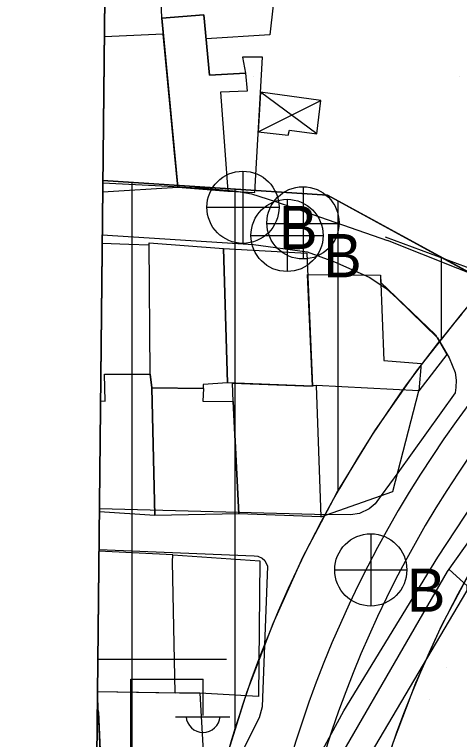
# Model space of a CAD drawing. Extents: x 417997 to 421451, y 4451742 to 4455216.
# Drawn here: x 419108.7 to 419151.9, y 4452992.2 to 4453062.5 of the extents above; entities that cross this region are included whole.
import ezdxf

# ---------------------------------------------------------------- set-up
doc = ezdxf.new("R2010")
doc.units = 0
for name, color, linetype in [('ADA', 7, 'Continuous'), ('ADAKENARI', 7, 'Continuous'), ('B_Mesken', 7, 'Continuous'), ('B_Sundurma', 7, 'Continuous'), ('B_Teras', 7, 'Continuous'), ('Default', 7, 'Continuous'), ('KALDIRIM', 7, 'Continuous'), ('O_Park_Bahce', 7, 'Continuous'), ('P_Grid', 7, 'Continuous'), ('PAFTALAMA', 7, 'Continuous'), ('PL_AYA_PARK_DINLENME', 7, 'Continuous'), ('PL_KON_MEV_350', 7, 'Continuous'), ('PL_SAY_ORTAOGRETIM', 7, 'Continuous'), ('S_Elektrik_Diregi', 7, 'Continuous'), ('S_Rogar_Kapagi', 7, 'Continuous'), ('S_Rogar_Kapagi_Buski', 7, 'Continuous'), ('Sinir_Duvar_tek_tarafa_ait', 7, 'Continuous'), ('Sinir_Tel_bir_taraf', 7, 'Continuous'), ('SN_3_DERECE_KAYNAK_KORUMA', 7, 'Continuous'), ('TR_ORTAEGITIM', 7, 'Continuous'), ('TR_ORTAYOGUNKONUT', 7, 'Continuous'), ('TR_PARKALANI', 7, 'Continuous'), ('Y_Lejant', 7, 'Continuous'), ('Yol_Sose', 7, 'Continuous')]:
    doc.layers.add(name, color=color, linetype=linetype)

# ---------------------------------------------------------------- blocks, each defined once
blk = doc.blocks.new('POINT_DISPLAY')
at = {"layer": 'Default'}
blk.add_line((0, 0), (0, 0), dxfattribs=at)

msp = doc.modelspace()

# ---------------------------------------------------------------- linework, layer by layer
at = {"layer": 'ADA'}
for p, q in [((419139.075, 4453044.969), (419117.291, 4453046.386)), ((419139.075, 4453044.969), (419117.291, 4453046.386)), ((419154.645, 4453036.476), (419139.075, 4453044.969)), ((419154.645, 4453036.476), (419139.075, 4453044.969))]:
    msp.add_line(p, q, dxfattribs=at)
at = {"layer": 'ADAKENARI'}
for centre, radius in [((419239.972, 4452959.278), 114.998), ((419239.972, 4452959.278), 114.998), ((419239.974, 4452959.277), 100), ((419239.974, 4452959.277), 100)]:
    msp.add_arc(centre, radius, 139.84982, 178.48545, dxfattribs=at)
at = {"layer": 'B_Mesken'}
for points in [[(419122.886, 4453065.646), (419131.262, 4453065.954), (419131.282, 4453066.278), (419134.125, 4453066.305), (419133.472, 4453060.53), (419127.307, 4453060.119), (419127.085, 4453062.473), (419123.008, 4453062.14)], [(419129.418, 4453045.377), (419132.029, 4453045.248), (419132.781, 4453058.357), (419130.841, 4453058.355), (419131.132, 4453056.792), (419127.637, 4453056.615), (419127.085, 4453062.473), (419123.008, 4453062.14), (419124.561, 4453045.747)], [(419121.893, 4453027.607), (419121.769, 4453040.345), (419129.002, 4453039.813), (419129.368, 4453026.782), (419127.03, 4453026.634), (419127.024, 4453026.219), (419122.051, 4453026.291)], [(419129.002, 4453039.813), (419137.064, 4453039.365), (419137.614, 4453026.472), (419129.368, 4453026.782)], [(419144.231, 4453036.536), (419149.567, 4453031.444), (419150.642, 4453029.514), (419147.947, 4453026.007), (419137.98, 4453026.513), (419137.614, 4453026.472), (419137.153, 4453037.272), (419144.204, 4453037.222)], [(419122.331, 4453013.908), (419122.051, 4453026.291), (419127.038, 4453026.218), (419126.999, 4453025), (419129.942, 4453024.987), (419130.484, 4453014.067)], [(419138.424, 4453013.795), (419130.484, 4453014.067), (419129.942, 4453024.987), (419129.88, 4453026.763), (419137.614, 4453026.472), (419137.611, 4453026.542), (419137.98, 4453026.513)], [(419137.98, 4453026.513), (419138.424, 4453013.795), (419145.417, 4453016.242), (419147.947, 4453026.007)], [(419124.313, 4452996.731), (419124.043, 4453009.437), (419124.066, 4453010.118), (419132.519, 4453009.525), (419132.388, 4452996.369), (419126.705, 4452996.688)], [(419117.349, 4452983.794), (419116.768, 4452996.867), (419126.705, 4452996.688), (419127.432, 4452983.718)]]:
    msp.add_lwpolyline(points, close=True, dxfattribs=at)
for points in [[(419117.281, 4453045.294), (419124.561, 4453045.747), (419123.156, 4453060.578), (419117.442, 4453060.325)], [(419117.064, 4453025.025), (419117.502, 4453025.008), (419117.443, 4453027.628), (419121.893, 4453027.607), (419122.051, 4453026.291), (419122.331, 4453013.908), (419116.949, 4453014.282)], [(419116.763, 4452996.869), (419116.768, 4452996.867), (419124.313, 4452996.731), (419124.043, 4453009.437), (419124.066, 4453010.118), (419116.909, 4453010.475)], [(419116.742, 4452994.893), (419116.856, 4452994.893), (419117.349, 4452983.794), (419116.623, 4452983.796)]]:
    msp.add_lwpolyline(points, dxfattribs=at)
at = {"layer": 'B_Sundurma'}
for p, q in [((419138.044, 4453050.922), (419132.586, 4453054.959)), ((419132.366, 4453051.124), (419138.444, 4453054.168))]:
    msp.add_line(p, q, dxfattribs=at)
msp.add_lwpolyline([(419132.366, 4453051.124), (419135.276, 4453050.79), (419135.39, 4453051.275), (419138.044, 4453050.922), (419138.444, 4453054.168), (419132.586, 4453054.959)], close=True, dxfattribs=at)
at = {"layer": 'B_Teras'}
for points in [[(419124.219, 4453049.361), (419123.008, 4453062.14), (419127.085, 4453062.473), (419127.637, 4453056.615), (419131.132, 4453056.792), (419131.282, 4453055.053), (419128.715, 4453054.966), (419129.13, 4453049.309), (419129.418, 4453045.377), (419124.561, 4453045.747)], [(419137.153, 4453037.272), (419144.204, 4453037.222), (419144.529, 4453028.954), (419148.164, 4453028.67), (419147.947, 4453026.007), (419137.98, 4453026.513), (419137.614, 4453026.472)]]:
    msp.add_lwpolyline(points, close=True, dxfattribs=at)
at = {"layer": 'KALDIRIM'}
for centre, radius, start, end in [((419239.976, 4452959.28), 109.001, 139.84789, 174.5032), ((419239.976, 4452959.28), 109.001, 139.84789, 174.5032), ((419239.974, 4452959.275), 106, 139.85094, 174.37368), ((419239.974, 4452959.275), 106, 139.85094, 174.37368)]:
    msp.add_arc(centre, radius, start, end, dxfattribs=at)
at = {"layer": 'O_Park_Bahce'}
msp.add_lwpolyline([(419137.324, 4452966.227), (419139.401, 4452966.387), (419139.548, 4452966.621), (419138.756, 4452977.796), (419138.782, 4452977.994), (419141.248, 4452982.125), (419141.514, 4452982.954), (419141.248, 4452987.044), (419141.282, 4452987.461), (419141.557, 4452987.951), (419152.584, 4453006.592), (419152.61, 4453006.77), (419152.641, 4453007.108), (419150.871, 4453008.684)], dxfattribs=at)
at = {"layer": 'P_Grid'}
msp.add_line((419116.796, 4453000), (419129.296, 4453000), dxfattribs=at)
at = {"layer": 'PAFTALAMA'}
for p, q in [((419138.441, 4455021.891), (419108.72, 4452245.779)), ((419138.441, 4455021.891), (419108.72, 4452245.779)), ((419116.795, 4453000), (419116.795, 4453000)), ((419116.795, 4453000), (419129.295, 4453000)), ((419116.795, 4453000), (419116.795, 4453000)), ((419116.795, 4453000), (419129.295, 4453000))]:
    msp.add_line(p, q, dxfattribs=at)
at = {"layer": 'PL_AYA_PARK_DINLENME'}
msp.add_lwpolyline([(419140.009, 4452961.92), (419140.359, 4452968.039), (419141.083, 4452974.126), (419142.178, 4452980.156), (419143.641, 4452986.108), (419145.466, 4452991.959), (419147.646, 4452997.688), (419150.172, 4453003.272), (419153.036, 4453008.691), (419156.227, 4453013.924), (419159.732, 4453018.952), (419163.539, 4453023.756), (419163.538, 4453023.756), (419187.355, 4453014.338), (419166.334, 4452946.426), (419139.641, 4452947.996)], close=True, dxfattribs=at)
msp.add_lwpolyline([(419140.009, 4452961.92), (419140.359, 4452968.039), (419141.083, 4452974.126), (419142.178, 4452980.156), (419143.641, 4452986.108), (419145.466, 4452991.959), (419147.646, 4452997.688), (419150.172, 4453003.272), (419153.036, 4453008.691), (419156.227, 4453013.924), (419159.732, 4453018.952), (419163.539, 4453023.756), (419163.538, 4453023.756), (419187.355, 4453014.338), (419166.334, 4452946.426), (419139.641, 4452947.996)], close=True, dxfattribs=at)
at = {"layer": 'PL_KON_MEV_350'}
msp.add_line((419117.291, 4453046.386), (419115.662, 4452894.206), dxfattribs=at)
msp.add_lwpolyline([(419115.662, 4452894.206), (419123.365, 4452899.906), (419125.015, 4452962.317), (419125.417, 4452969.354), (419126.249, 4452976.353), (419127.509, 4452983.288), (419129.191, 4452990.133), (419131.29, 4452996.862), (419133.796, 4453003.45), (419136.702, 4453009.871), (419139.995, 4453016.103), (419143.664, 4453022.121), (419147.695, 4453027.903), (419152.073, 4453033.428), (419154.645, 4453036.476), (419139.075, 4453044.969), (419117.291, 4453046.386)], dxfattribs=at)
at = {"layer": 'PL_SAY_ORTAOGRETIM'}
msp.add_line((419118.18, 4453129.375), (419117.291, 4453046.386), dxfattribs=at)
msp.add_line((419118.18, 4453129.375), (419117.291, 4453046.386), dxfattribs=at)
msp.add_lwpolyline([(419117.291, 4453046.386), (419139.075, 4453044.969), (419154.645, 4453036.476), (419183.327, 4453070.477), (419191.386, 4453087.989), (419197.343, 4453124.46), (419161.479, 4453129.666), (419118.18, 4453129.375)], dxfattribs=at)
msp.add_lwpolyline([(419117.291, 4453046.386), (419139.075, 4453044.969), (419154.645, 4453036.476), (419183.327, 4453070.477), (419191.386, 4453087.989), (419197.343, 4453124.46), (419161.479, 4453129.666), (419118.18, 4453129.375)], dxfattribs=at)
at = {"layer": 'S_Elektrik_Diregi'}
for p, q in [((419120.008, 4452980.535), (419120.008, 4452998.035)), ((419120.008, 4452998.035), (419127.008, 4452998.035)), ((419127.008, 4452994.535), (419127.008, 4452998.035)), ((419124.348, 4452994.395), (419129.598, 4452994.395))]:
    msp.add_line(p, q, dxfattribs=at)
msp.add_arc((419127.009, 4452994.548), 1.658, 184.83843, 355.14641, dxfattribs=at)
at = {"layer": 'S_Rogar_Kapagi'}
for p, q in [((419136.752, 4453038.763), (419136.752, 4453045.763)), ((419133.182, 4453042.228), (419140.182, 4453042.228))]:
    msp.add_line(p, q, dxfattribs=at)
msp.add_circle((419136.699, 4453042.292), 3.5, dxfattribs=at)
at = {"layer": 'S_Rogar_Kapagi_Buski'}
for p, q in [((419130.875, 4453047.305), (419130.875, 4453040.305)), ((419135.155, 4453044.575), (419135.155, 4453037.575)), ((419127.375, 4453043.805), (419134.375, 4453043.805)), ((419131.655, 4453041.075), (419138.655, 4453041.075)), ((419143.275, 4453012.144), (419143.275, 4453005.144)), ((419139.775, 4453008.644), (419146.775, 4453008.644))]:
    msp.add_line(p, q, dxfattribs=at)
for centre in [(419130.875, 4453043.805), (419135.155, 4453041.075), (419143.275, 4453008.644)]:
    msp.add_circle(centre, 3.5, dxfattribs=at)
at = {"layer": 'Sinir_Duvar_tek_tarafa_ait'}
for points in [[(419117.228, 4453040.339), (419119.801, 4453040.217)], [(419155.173, 4453037.026), (419144.709, 4453040.901)], [(419119.801, 4453040.217), (419121.771, 4453040.165)], [(419150.732, 4453008.488), (419154.931, 4453014.418)]]:
    msp.add_lwpolyline(points, dxfattribs=at)
at = {"layer": 'Sinir_Tel_bir_taraf'}
msp.add_lwpolyline([(419137.332, 4452966.111), (419136.137, 4452983.291), (419150.732, 4453008.488)], dxfattribs=at)
at = {"layer": 'SN_3_DERECE_KAYNAK_KORUMA'}
msp.add_line((419126.495, 4453906.073), (419108.72, 4452245.779), dxfattribs=at)
msp.add_line((419126.495, 4453906.073), (419108.72, 4452245.779), dxfattribs=at)
at = {"layer": 'TR_ORTAYOGUNKONUT'}
for p, q in [((419120.129, 4452897.511), (419120.129, 4453046.201)), ((419120.129, 4452897.511), (419120.129, 4453046.201)), ((419130.129, 4452993.139), (419130.129, 4453045.551)), ((419130.129, 4452993.139), (419130.129, 4453045.551)), ((419140.129, 4453016.322), (419140.129, 4453044.394)), ((419140.129, 4453016.322), (419140.129, 4453044.394)), ((419150.129, 4453030.974), (419150.129, 4453038.94)), ((419150.129, 4453030.974), (419150.129, 4453038.94))]:
    msp.add_line(p, q, dxfattribs=at)
at = {"layer": 'Y_Lejant'}
msp.add_lwpolyline([(419138.442, 4455021.89), (421266.409, 4454999.402), (421237.471, 4452223.294), (419108.722, 4452245.778)], close=True, dxfattribs=at)
at = {"layer": 'Yol_Sose'}
for points in [[(419123.62, 4453045.808), (419117.29, 4453046.125)], [(419126.427, 4453045.667), (419123.62, 4453045.808)], [(419126.909, 4453045.675), (419126.427, 4453045.667)], [(419126.909, 4453045.675), (419130.247, 4453045.36), (419131.713, 4453045.098), (419134.02, 4453044.375), (419144.893, 4453040.572)], [(419117.237, 4453041.131), (419131.909, 4453040.189), (419137.106, 4453039.482), (419139.765, 4453038.529), (419143.124, 4453037.019), (419144.723, 4453035.957), (419145.826, 4453034.949), (419149.748, 4453031.152), (419150.88, 4453029.208), (419151.452, 4453027.798), (419151.547, 4453027.038), (419151.524, 4453026.322), (419151.467, 4453025.806), (419145.891, 4453018.07)], [(419155.169, 4453036.58), (419155.036, 4453036.557), (419144.893, 4453040.572)], [(419145.891, 4453018.07), (419144.289, 4453015.847), (419143.705, 4453015.037), (419143.131, 4453014.555), (419142.18, 4453014.105), (419141.299, 4453013.971), (419139.062, 4453014.018)], [(419149.787, 4453009.891), (419154.967, 4453017.729)], [(419116.953, 4453014.593), (419139.062, 4453014.018)], [(419116.91, 4453010.63), (419131.98, 4453009.995), (419132.318, 4453009.986), (419132.75, 4453009.794), (419133.002, 4453009.568), (419133.263, 4453009.022), (419132.768, 4452996.252), (419132.739, 4452995.356), (419132.466, 4452994.309), (419127.398, 4452984.329)], [(419143.548, 4452905.505), (419134.277, 4452906.589), (419134.219, 4452906.63), (419133.957, 4452907.156), (419133.948, 4452908.112), (419136.093, 4452936.089), (419136.885, 4452947.577), (419137.006, 4452949.485), (419135.69, 4452966.609), (419134.698, 4452983.286), (419134.739, 4452983.962), (419135.145, 4452984.806), (419140.677, 4452994.982), (419149.787, 4453009.891)]]:
    msp.add_lwpolyline(points, dxfattribs=at)

# ---------------------------------------------------------------- block references
at = {"layer": 'TR_ORTAEGITIM', "xscale": 0.1, "yscale": 0.10000000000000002}
for p in [(419131.864, 4453056.476), (419131.864, 4453056.476), (419151.864, 4453056.476), (419151.864, 4453056.476)]:
    msp.add_blockref('POINT_DISPLAY', p, dxfattribs=at)
at = {"layer": 'TR_PARKALANI', "xscale": 0.1, "yscale": 0.10000000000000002}
for p in [(419150.655, 4452999.139), (419150.655, 4452999.139), (419148.982, 4452996.046), (419148.982, 4452996.046)]:
    msp.add_blockref('POINT_DISPLAY', p, dxfattribs=at)

# ---------------------------------------------------------------- texts
at = {"layer": 'S_Rogar_Kapagi_Buski'}
for p in [(419134.375, 4453039.74), (419138.655, 4453037.01), (419146.775, 4453004.58)]:
    msp.add_text('B', height=4.2, dxfattribs=at).set_placement(p)

doc.saveas('drawing.dxf')
